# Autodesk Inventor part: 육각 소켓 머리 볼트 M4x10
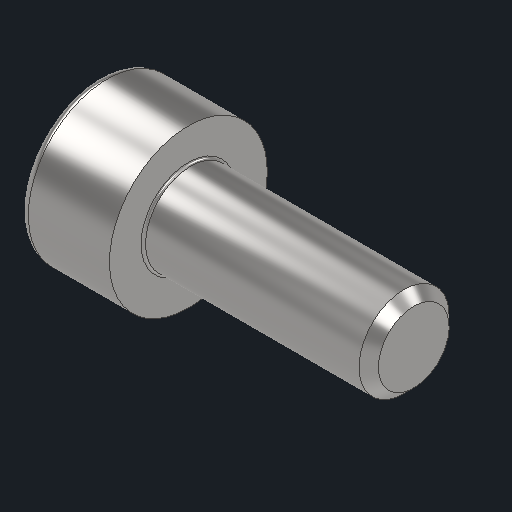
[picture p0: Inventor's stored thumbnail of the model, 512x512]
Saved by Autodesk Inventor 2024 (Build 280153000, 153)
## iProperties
Created: 2025-02
Part Number: 육각 소켓 머리 볼트 M4x10
Material: 강철, 연강
Description: 6각머리 태핑 나사
Document SubType Name: Modeling
Designer: kh_501
Density: 7.85 g/cm^3
Appearance: 기본값
Author: jhkim
Sending System: Autodesk Inventor 2025
Preprocessor: ST-DEVELOPER v20
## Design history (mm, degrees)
feature "Solid1"
node "솔리드1"
